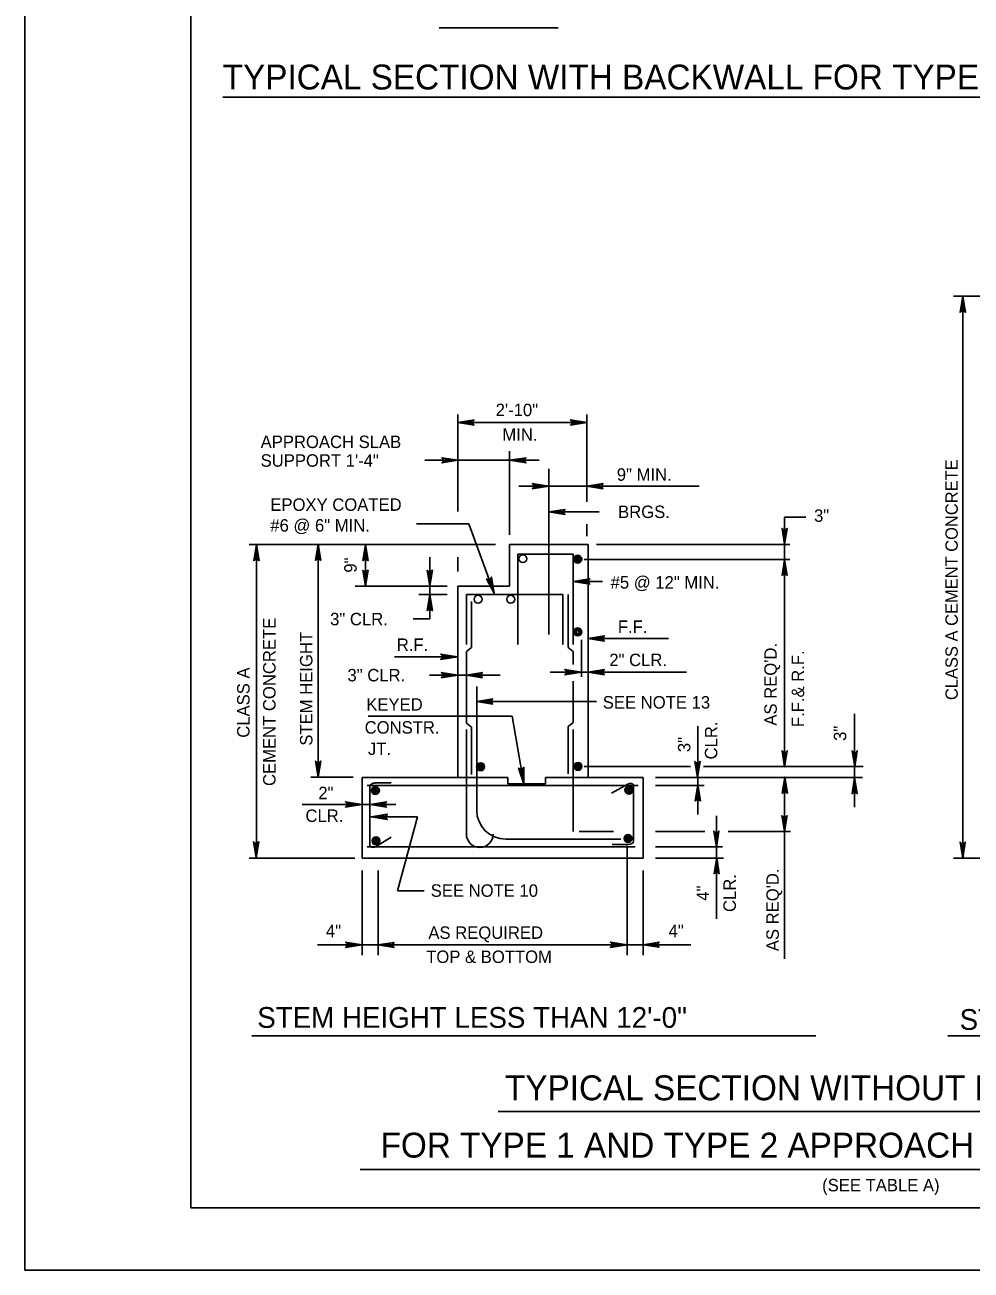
# Model space of a CAD drawing. Extents: x 235 to 2276, y 116 to 1308.
# Drawn here: x 579.4 to 807.5, y 116.4 to 416.6 of the extents above; entities that cross this region are included whole.
import ezdxf

# ---------------------------------------------------------------- set-up
doc = ezdxf.new("R2010")
doc.units = 0
doc.layers.add('1', color=7, linetype='Continuous')
doc.layers.add('PLT-BNDY', color=7, linetype='Continuous')

msp = doc.modelspace()

# ---------------------------------------------------------------- linework, layer by layer
at = {"layer": '1'}
for p, q in [((619.42, 131.41), (619.42, 695.41)), ((679.27, 415.87), (708.02, 415.87)), ((627.1, 399.19), (991.42, 399.19)), ((888.68, 351.17), (803.33, 351.17)), ((805.52, 215.76), (805.52, 351.17)), ((683.82, 299.33), (683.82, 322.69)), ((714.92, 301.6), (714.92, 322.69)), ((683.82, 320.75), (714.92, 320.75)), ((696.24, 293.65), (696.24, 313.81)), ((683.82, 311.64), (675.83, 311.64)), ((696.24, 311.64), (683.82, 311.64)), ((696.24, 311.64), (703.43, 311.64)), ((705.73, 269.67), (705.73, 309.55)), ((698.54, 305.4), (705.73, 305.4)), ((705.73, 305.4), (741.98, 305.4)), ((705.73, 299.18), (717.9, 299.18)), ((762.58, 287.76), (762.58, 297.9)), ((762.58, 297.9), (767.71, 297.9)), ((686.48, 296.31), (673.84, 296.31)), ((686.48, 296.31), (692.58, 279.6)), ((714.92, 293.37), (714.92, 296.21)), ((692.86, 291.35), (633.51, 291.35)), ((635.23, 291.35), (635.23, 215.76)), ((650.14, 235.27), (650.14, 291.35)), ((661.55, 281.28), (661.55, 291.35)), ((696.24, 291.35), (715.22, 291.35)), ((696.24, 281.28), (696.24, 291.35)), ((715.22, 235.14), (715.22, 291.35)), ((717.23, 291.35), (763.83, 291.35)), ((677.06, 281.28), (677.06, 288.26)), ((683.82, 284.85), (683.82, 288.26)), ((698.27, 289.01), (711.64, 289.01)), ((698.27, 267.25), (698.27, 289.01)), ((711.64, 267.25), (711.64, 289.01)), ((714.28, 287.76), (763.83, 287.76)), ((762.58, 237.79), (762.58, 287.76)), ((718.7, 282.41), (711.64, 282.41)), ((681.22, 281.28), (659.08, 281.28)), ((681.22, 279.28), (674.41, 279.28)), ((677.06, 279.28), (677.06, 281.28)), ((677.06, 273.38), (677.06, 279.28)), ((683.82, 235.14), (683.82, 281.28)), ((683.82, 281.28), (696.24, 281.28)), ((685.85, 267.25), (685.85, 279.28)), ((685.85, 279.28), (709.14, 279.28)), ((709.14, 267.25), (709.14, 279.28)), ((710.39, 266.49), (710.39, 279.28)), ((687.1, 266.49), (687.1, 277.61)), ((673.06, 273.38), (677.06, 273.38)), ((713.59, 259.44), (713.59, 268.39)), ((715.22, 268.69), (734.61, 268.69)), ((668.51, 264.29), (683.82, 264.29)), ((687.1, 266.49), (685.85, 265.55)), ((685.85, 248.26), (685.85, 265.55)), ((710.39, 266.49), (711.64, 265.55)), ((711.64, 262.43), (711.64, 265.55)), ((676.97, 259.84), (683.82, 259.84)), ((683.82, 259.84), (694.04, 259.84)), ((713.59, 260.56), (706.09, 260.56)), ((711.64, 248.42), (711.64, 258.42)), ((715.22, 260.56), (713.59, 260.56)), ((738.93, 260.56), (715.22, 260.56)), ((688.35, 227.28), (688.35, 257.11)), ((717.19, 253.49), (688.35, 253.49)), ((696.9, 249.98), (662.15, 249.98)), ((699.67, 233.61), (696.9, 249.98)), ((779.45, 237.79), (779.45, 250.5)), ((687.1, 247.32), (685.85, 248.26)), ((685.85, 221.54), (685.85, 246.7)), ((687.1, 235.92), (687.1, 247.32)), ((710.39, 247.48), (711.64, 248.42)), ((710.39, 236.07), (710.39, 247.48)), ((711.64, 222.17), (711.64, 246.7)), ((741.64, 235.14), (741.64, 247.56)), ((714.29, 237.79), (739.92, 237.79)), ((743.04, 237.79), (781.48, 237.79)), ((779.43, 227.98), (779.43, 237.79)), ((648.39, 235.27), (658.59, 235.27)), ((660.7, 215.76), (660.7, 235.14)), ((660.7, 235.14), (695.86, 235.14)), ((695.86, 235.14), (695.86, 233.61)), ((704.92, 235.14), (728.51, 235.14)), ((704.92, 235.14), (704.92, 233.61)), ((728.51, 215.76), (728.51, 235.14)), ((731.43, 235.14), (781.33, 235.14)), ((741.64, 226.23), (741.64, 235.14)), ((762.58, 222.17), (762.58, 235.14)), ((661.95, 233.26), (727.26, 233.26)), ((662.58, 233.11), (662.58, 218.89)), ((667.73, 233.89), (663.83, 233.89)), ((695.86, 233.61), (704.92, 233.61)), ((724.76, 233.57), (720.86, 231.39)), ((726.17, 219.82), (726.17, 233.26)), ((731.43, 233.26), (743.2, 233.26)), ((646.27, 228.65), (660.7, 228.65)), ((660.7, 228.65), (668.88, 228.65)), ((662.89, 225.66), (674.07, 225.66)), ((674.07, 225.66), (669.29, 207.84)), ((746.17, 215.76), (746.17, 225.92)), ((713.04, 222.17), (721.33, 222.17)), ((731.43, 222.17), (743.36, 222.17)), ((748.98, 222.17), (763.98, 222.17)), ((762.58, 191.45), (762.58, 222.17)), ((663.98, 218.42), (667.73, 220.76)), ((723.07, 220.28), (695.35, 220.28)), ((661.92, 218.42), (726.51, 218.42)), ((721.01, 219.04), (724.76, 219.04)), ((724.61, 218.73), (724.61, 192.3)), ((731.43, 218.42), (747.58, 218.42)), ((655.54, 215.76), (633.51, 215.76)), ((658.98, 215.76), (655.54, 215.76)), ((660.7, 215.76), (728.51, 215.76)), ((731.43, 215.76), (747.88, 215.76)), ((746.17, 201.1), (746.17, 215.76)), ((828.94, 215.76), (803.33, 215.76)), ((660.7, 212.76), (660.7, 192.3)), ((664.61, 212.76), (664.61, 192.3)), ((728.51, 212.76), (728.51, 192.3)), ((669.29, 207.84), (675.7, 207.84)), ((664.61, 194.82), (650, 194.82)), ((664.61, 194.82), (724.61, 194.82)), ((724.61, 194.82), (739.99, 194.82)), ((634.1, 172.87), (770.08, 172.87)), ((801.95, 172.87), (957.24, 172.87)), ((693.48, 154.61), (886.82, 154.61)), ((660.27, 140.7), (917.48, 140.7)), ((1405.42, 131.41), (619.42, 131.41))]:
    msp.add_line(p, q, dxfattribs=at)
for points in [[(805.02, 347.44), (805.27, 347.56), (805.52, 351.19), (805.02, 347.44), (804.9, 347.31), (805.52, 351.19), (805.65, 347.56), (806.02, 347.44), (805.52, 351.19), (806.15, 347.31), (806.02, 347.44)], [(687.57, 320.25), (687.45, 320.5), (683.82, 320.75), (687.57, 320.25), (687.7, 320.13), (683.82, 320.75), (687.45, 320.88), (687.57, 321.25), (683.82, 320.75), (687.7, 321.38), (687.57, 321.25)], [(711.17, 321.25), (711.29, 321), (714.92, 320.75), (711.17, 321.25), (710.92, 321.38), (714.92, 320.75), (711.29, 320.63), (711.17, 320.38), (714.92, 320.75), (710.92, 320.13), (711.17, 320.38)], [(680.07, 311.14), (680.2, 311.39), (683.82, 311.64), (680.07, 311.14), (679.95, 311.02), (683.82, 311.64), (680.2, 311.77), (680.07, 312.14), (683.82, 311.64), (679.95, 312.27), (680.07, 312.14)], [(699.99, 312.14), (699.87, 311.89), (696.24, 311.64), (699.99, 312.14), (700.24, 312.27), (696.24, 311.64), (699.87, 311.52), (699.99, 311.27), (696.24, 311.64), (700.24, 311.02), (699.99, 311.27)], [(701.98, 305.9), (702.11, 305.65), (705.73, 305.4), (701.98, 305.9), (701.73, 306.02), (705.73, 305.4), (702.11, 305.27), (701.98, 305.02), (705.73, 305.4), (701.73, 304.77), (701.98, 305.02)], [(718.67, 304.9), (718.54, 305.15), (714.92, 305.4), (718.67, 304.9), (718.79, 304.77), (714.92, 305.4), (718.54, 305.52), (718.67, 305.9), (714.92, 305.4), (718.79, 306.02), (718.67, 305.9)], [(709.48, 298.68), (709.36, 298.93), (705.73, 299.18), (709.48, 298.68), (709.61, 298.56), (705.73, 299.18), (709.36, 299.31), (709.48, 299.68), (705.73, 299.18), (709.61, 299.81), (709.48, 299.68)], [(763.08, 295.1), (762.83, 294.85), (762.58, 291.35), (763.08, 295.1), (763.2, 295.23), (762.58, 291.35), (762.45, 294.85), (762.2, 294.98), (762.58, 291.35), (761.95, 295.23), (762.2, 294.98)], [(634.73, 287.6), (634.98, 287.73), (635.23, 291.35), (634.73, 287.6), (634.61, 287.48), (635.23, 291.35), (635.36, 287.73), (635.73, 287.6), (635.23, 291.35), (635.86, 287.48), (635.73, 287.6)], [(649.61, 287.66), (649.86, 287.78), (650.11, 291.41), (649.61, 287.66), (649.48, 287.53), (650.11, 291.41), (650.23, 287.78), (650.61, 287.66), (650.11, 291.41), (650.73, 287.53), (650.61, 287.66)], [(661.05, 287.6), (661.3, 287.73), (661.55, 291.35), (661.05, 287.6), (660.92, 287.48), (661.55, 291.35), (661.67, 287.73), (662.05, 287.6), (661.55, 291.35), (662.17, 287.48), (662.05, 287.6)], [(762.08, 284.01), (762.33, 284.14), (762.58, 287.76), (762.08, 284.01), (761.95, 283.89), (762.58, 287.76), (762.7, 284.14), (763.08, 284.01), (762.58, 287.76), (763.2, 283.89), (763.08, 284.01)], [(662.05, 285.03), (661.8, 284.78), (661.55, 281.28), (662.05, 285.03), (662.17, 285.15), (661.55, 281.28), (661.42, 284.78), (661.17, 284.9), (661.55, 281.28), (660.92, 285.15), (661.17, 284.9)], [(677.56, 285.03), (677.31, 284.78), (677.06, 281.28), (677.56, 285.03), (677.68, 285.15), (677.06, 281.28), (676.93, 284.78), (676.68, 284.9), (677.06, 281.28), (676.43, 285.15), (676.68, 284.9)], [(691.84, 283.31), (691.68, 282.99), (692.58, 279.6), (691.84, 283.31), (691.92, 283.47), (692.58, 279.6), (691.33, 282.87), (691.05, 282.91), (692.58, 279.6), (690.73, 283.06), (691.05, 282.91)], [(715.39, 282.91), (715.26, 282.66), (711.64, 282.41), (715.39, 282.91), (715.64, 283.04), (711.64, 282.41), (715.26, 282.29), (715.39, 282.04), (711.64, 282.41), (715.64, 281.79), (715.39, 282.04)], [(676.56, 275.53), (676.81, 275.65), (677.06, 279.28), (676.56, 275.53), (676.43, 275.4), (677.06, 279.28), (677.18, 275.65), (677.56, 275.53), (677.06, 279.28), (677.68, 275.4), (677.56, 275.53)], [(718.97, 268.19), (718.84, 268.44), (715.22, 268.69), (718.97, 268.19), (719.09, 268.07), (715.22, 268.69), (718.84, 268.82), (718.97, 269.19), (715.22, 268.69), (719.09, 269.32), (718.97, 269.19)], [(679.93, 264.77), (680.06, 264.52), (683.68, 264.27), (679.93, 264.77), (679.68, 264.9), (683.68, 264.27), (680.06, 264.15), (679.93, 263.9), (683.68, 264.27), (679.68, 263.65), (679.93, 263.9)], [(709.84, 261.06), (709.97, 260.81), (713.59, 260.56), (709.84, 261.06), (709.59, 261.19), (713.59, 260.56), (709.97, 260.44), (709.84, 260.19), (713.59, 260.56), (709.59, 259.94), (709.84, 260.19)], [(718.97, 260.06), (718.84, 260.31), (715.22, 260.56), (718.97, 260.06), (719.09, 259.94), (715.22, 260.56), (718.84, 260.69), (718.97, 261.06), (715.22, 260.56), (719.09, 261.19), (718.97, 261.06)], [(680.05, 260.33), (680.18, 260.08), (683.8, 259.83), (680.05, 260.33), (679.8, 260.46), (683.8, 259.83), (680.18, 259.71), (680.05, 259.46), (683.8, 259.83), (679.8, 259.21), (680.05, 259.46)], [(689.6, 259.36), (689.47, 259.61), (685.85, 259.86), (689.6, 259.36), (689.72, 259.23), (685.85, 259.86), (689.47, 259.98), (689.6, 260.36), (685.85, 259.86), (689.72, 260.48), (689.6, 260.36)], [(692.1, 252.99), (691.98, 253.24), (688.35, 253.49), (692.1, 252.99), (692.23, 252.86), (688.35, 253.49), (691.98, 253.61), (692.1, 253.99), (688.35, 253.49), (692.23, 254.11), (692.1, 253.99)], [(763.08, 241.48), (762.83, 241.23), (762.58, 237.73), (763.08, 241.48), (763.21, 241.61), (762.58, 237.73), (762.46, 241.23), (762.21, 241.36), (762.58, 237.73), (761.96, 241.61), (762.21, 241.36)], [(779.97, 241.47), (779.72, 241.22), (779.47, 237.72), (779.97, 241.47), (780.09, 241.6), (779.47, 237.72), (779.34, 241.22), (779.09, 241.35), (779.47, 237.72), (778.84, 241.6), (779.09, 241.35)], [(650.64, 239.02), (650.39, 238.77), (650.14, 235.27), (650.64, 239.02), (650.76, 239.14), (650.14, 235.27), (650.01, 238.77), (649.76, 238.89), (650.14, 235.27), (649.51, 239.14), (649.76, 238.89)], [(699.57, 237.42), (699.32, 237.23), (699.67, 233.61), (699.57, 237.42), (699.7, 237.63), (699.67, 233.61), (698.94, 237.17), (698.65, 237.26), (699.67, 233.61), (698.44, 237.44), (698.65, 237.26)], [(742.08, 238.93), (741.83, 238.68), (741.58, 235.18), (742.08, 238.93), (742.21, 239.05), (741.58, 235.18), (741.46, 238.68), (741.21, 238.8), (741.58, 235.18), (740.96, 239.05), (741.21, 238.8)], [(762.11, 231.51), (762.36, 231.63), (762.61, 235.26), (762.11, 231.51), (761.99, 231.38), (762.61, 235.26), (762.74, 231.63), (763.11, 231.51), (762.61, 235.26), (763.24, 231.38), (763.11, 231.51)], [(778.95, 231.39), (779.2, 231.51), (779.45, 235.14), (778.95, 231.39), (778.83, 231.26), (779.45, 235.14), (779.58, 231.51), (779.95, 231.39), (779.45, 235.14), (780.08, 231.26), (779.95, 231.39)], [(741.16, 229.63), (741.41, 229.76), (741.66, 233.38), (741.16, 229.63), (741.03, 229.51), (741.66, 233.38), (741.78, 229.76), (742.16, 229.63), (741.66, 233.38), (742.28, 229.51), (742.16, 229.63)], [(656.93, 229.14), (657.05, 228.89), (660.68, 228.64), (656.93, 229.14), (656.68, 229.27), (660.68, 228.64), (657.05, 228.52), (656.93, 228.27), (660.68, 228.64), (656.68, 228.02), (656.93, 228.27)], [(666.47, 228.17), (666.35, 228.42), (662.72, 228.67), (666.47, 228.17), (666.6, 228.04), (662.72, 228.67), (666.35, 228.79), (666.47, 229.17), (662.72, 228.67), (666.6, 229.29), (666.47, 229.17)], [(666.64, 225.16), (666.51, 225.41), (662.89, 225.66), (666.64, 225.16), (666.76, 225.04), (662.89, 225.66), (666.51, 225.79), (666.64, 226.16), (662.89, 225.66), (666.76, 226.29), (666.64, 226.16)], [(763.03, 225.88), (762.78, 225.63), (762.53, 222.13), (763.03, 225.88), (763.16, 226), (762.53, 222.13), (762.41, 225.63), (762.16, 225.75), (762.53, 222.13), (761.91, 226), (762.16, 225.75)], [(746.63, 222.13), (746.38, 221.88), (746.13, 218.38), (746.63, 222.13), (746.76, 222.25), (746.13, 218.38), (746.01, 221.88), (745.76, 222), (746.13, 218.38), (745.51, 222.25), (745.76, 222)], [(635.69, 219.55), (635.44, 219.3), (635.19, 215.8), (635.69, 219.55), (635.81, 219.68), (635.19, 215.8), (635.06, 219.3), (634.81, 219.43), (635.19, 215.8), (634.56, 219.68), (634.81, 219.43)], [(806.02, 219.48), (805.77, 219.23), (805.52, 215.73), (806.02, 219.48), (806.14, 219.61), (805.52, 215.73), (805.39, 219.23), (805.02, 219.36), (805.52, 215.73), (804.89, 219.61), (805.02, 219.36)], [(745.7, 212.11), (745.95, 212.23), (746.2, 215.86), (745.7, 212.11), (745.58, 211.98), (746.2, 215.86), (746.33, 212.23), (746.7, 212.11), (746.2, 215.86), (746.83, 211.98), (746.7, 212.11)], [(657, 195.32), (657.13, 195.07), (660.75, 194.82), (657, 195.32), (656.75, 195.45), (660.75, 194.82), (657.13, 194.7), (657, 194.45), (660.75, 194.82), (656.75, 194.2), (657, 194.45)], [(668.28, 194.31), (668.16, 194.56), (664.53, 194.81), (668.28, 194.31), (668.41, 194.18), (664.53, 194.81), (668.16, 194.93), (668.28, 195.31), (664.53, 194.81), (668.41, 195.43), (668.28, 195.31)], [(720.85, 195.34), (720.97, 195.09), (724.6, 194.84), (720.85, 195.34), (720.6, 195.47), (724.6, 194.84), (720.97, 194.72), (720.85, 194.47), (724.6, 194.84), (720.6, 194.22), (720.85, 194.47)], [(732.19, 194.35), (732.07, 194.6), (728.44, 194.85), (732.19, 194.35), (732.32, 194.23), (728.44, 194.85), (732.07, 194.98), (732.19, 195.35), (728.44, 194.85), (732.32, 195.48), (732.19, 195.35)]]:
    msp.add_lwpolyline(points, dxfattribs=at)
for centre, radius in [((699.46, 287.92), 0.954), ((712.7, 287.81), 0.954), ((712.7, 287.81), 0.681), ((712.7, 287.81), 0.372), ((712.7, 287.81), 0.188), ((712.7, 287.81), 0.0805), ((688.68, 278.13), 0.954), ((696.55, 278.13), 0.954), ((712.71, 270.26), 0.954), ((712.71, 270.26), 0.681), ((712.71, 270.26), 0.372), ((689.28, 237.76), 0.954), ((689.28, 237.76), 0.681), ((689.28, 237.76), 0.372), ((689.28, 237.76), 0.188), ((689.28, 237.76), 0.0805), ((712.76, 237.85), 0.954), ((712.76, 237.85), 0.681), ((712.76, 237.85), 0.372), ((712.76, 237.85), 0.188), ((712.76, 237.85), 0.0805), ((663.93, 232.04), 0.954), ((663.93, 232.04), 0.681), ((663.93, 232.04), 0.372), ((663.93, 232.04), 0.188), ((663.93, 232.04), 0.0805), ((725.05, 232.13), 0.954), ((725.05, 232.13), 0.681), ((725.05, 232.13), 0.372), ((725.05, 232.13), 0.188), ((725.05, 232.13), 0.0805), ((664.07, 219.89), 0.954), ((664.07, 219.89), 0.681), ((664.07, 219.89), 0.372), ((664.07, 219.89), 0.188), ((664.07, 219.89), 0.0805), ((724.84, 220.47), 0.954), ((724.84, 220.47), 0.681), ((724.84, 220.47), 0.372), ((724.84, 220.47), 0.188), ((724.84, 220.47), 0.0805)]:
    msp.add_circle(centre, radius, dxfattribs=at)
for centre, radius, end in [((695.35, 227.28), 7, 270), ((689.08, 221.54), 3.22, 0)]:
    msp.add_arc(centre, radius, 180, end, dxfattribs=at)
for centre, major_axis, ratio, start_param, end_param in [((663.87, 233.04), (-1.3, 0), 0.602565, 4.712389, 6.283185), ((725.33, 233.27), (-0.812, 0), 0.572437, 3.141593, 5.497787), ((724.84, 219.78), (1.3, 0), 0.572437, 4.712389, 6.283185), ((663.39, 218.84), (0.812, 0), 0.602565, 3.141593, 5.497787)]:
    msp.add_ellipse(centre, major_axis=major_axis, ratio=ratio, start_param=start_param, end_param=end_param, dxfattribs=at)
at = {"layer": 'PLT-BNDY'}
msp.add_lwpolyline([(579.42, 710.41), (1420.42, 710.41), (1420.42, 116.41), (579.42, 116.41)], close=True, dxfattribs=at)

# ---------------------------------------------------------------- texts
at = {"layer": '1'}
for s, height, p in [('TYPICAL SECTION WITH BACKWALL FOR TYPE 3 AND 4 APPROACH SLABS', 6, (627.11, 401.03)), ('2\'-10"', 3.003, (692.92, 322.28)), ('MIN.', 3, (694.53, 316.33)), ('APPROACH SLAB', 3, (636.26, 314.59)), ('SUPPORT 1\'-4"', 3, (636.26, 310.09)), ('9" MIN.', 3.003, (722.12, 306.7)), ('EPOXY COATED', 3, (638.59, 299.45)), ('  BRGS.', 3, (720.21, 297.72)), ('#6 @ 6" MIN.', 3, (638.59, 294.45)), ('3"', 3.003, (769.68, 296.8)), ('#5 @ 12" MIN.', 3, (720.64, 280.71)), ('3" CLR.', 3.003, (653, 271.86)), ('F.F.', 3, (722.38, 270.02)), ('R.F.', 3, (669.08, 265.68)), ('2" CLR.', 3, (720.32, 262.02)), ('3" CLR.', 3.003, (657.19, 258.34)), ('KEYED ', 3, (661.72, 251.29)), ('SEE NOTE 13', 3.003, (718.73, 251.79)), ('CONSTR. ', 3, (661.33, 245.74)), ('JT.', 3, (662.12, 240.59)), ('2"', 3.003, (650.17, 229.94)), ('CLR.', 3, (647.06, 224.46)), ('SEE NOTE 10', 3, (677.26, 206.41)), ('4"', 3.003, (651.99, 196.67)), (' AS REQUIRED ', 3, (675.58, 196.27)), ('4"', 3.003, (734.59, 196.67)), ('TOP & BOTTOM', 3, (676.17, 190.45)), ('STEM HEIGHT LESS THAN 12\'-0"', 5, (635.44, 174.82)), ('STEM HEIGHT GREATER THAN 12\'-0"', 5, (804.77, 174.33)), ('FOR TYPE 1 AND TYPE 2 APPROACH SLAB CORBEL', 6, (665.17, 143.54)), ('(SEE TABLE A)', 3, (771.63, 135.4))]:
    msp.add_text(s, height=height, dxfattribs=at).set_placement(p)
for s, height, rotation, p in [('CLASS A CEMENT CONCRETE', 2.97, 90, (804.32, 253.83)), ('9"', 3, 90, (659.41, 284.55)), ('CEMENT CONCRETE', 3, 90, (639.85, 233.12)), ('STEM HEIGHT', 3, 90, (648.74, 242.84)), ("AS REQ'D.", 3, 90, (760.69, 247.67)), ('F.F.& R.F.', 3, 90, (767.29, 247.32)), ('CLASS A', 3, 90, (633.59, 244.75)), ('CLR.', 3, 90, (746.35, 239.52)), ('3"', 3, 90, (777.44, 243.99)), ('3"', 3, 90, (739.86, 241.28)), ('CLR.', 3, 90, (750.83, 202.74)), ("AS REQ'D.", 3, 90, (761.18, 193.29)), ('4"', 3, 90, (744.35, 205.46)), ('TYPICAL SECTION WITHOUT BACKWALL', 6, 360, (695.17, 157.36))]:
    msp.add_text(s, height=height, rotation=rotation, dxfattribs=at).set_placement(p)

doc.saveas('drawing.dxf')
